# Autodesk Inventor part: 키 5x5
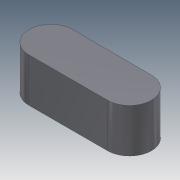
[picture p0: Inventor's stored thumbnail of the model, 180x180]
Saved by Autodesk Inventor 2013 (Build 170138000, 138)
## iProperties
Company: 한국ATC센터
Created: 2014-10
Part Number: 키 5x5
Document SubType Name: Modeling
Designer: KYOUNG IL JANG
Density: 1 g/cm^3
Mass: 0.323175 g
Surface Area: 2.9781 cm^2
Volume: 0.323175 cm^3
Material: 일반
Author: KYOUNG IL JANG
Revision Number: 1
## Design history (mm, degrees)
sketch "스케치1"
  geometry: L1 (-4.5, -2.5)-(4.5, -2.5); L2 (4.5, 2.5)-(-4.5, 2.5); A1 r 2.5 centre (4.5, 0) between (4.5, -2.5) and (4.5, 2.5); A2 r 2.5 centre (-4.5, 0) between (-4.5, 2.5) and (-4.5, -2.5); 2 further points
  constraints: 4 end point, 4 point on circle, 4 tangent, 2 centre point, 1 horizontal, 1 horizontal alignment, 1 midpoint, 1 parallel, 1 vertical alignment
  dimensions: "d0" = 5 distance between parallel lines of L1 L2; "d1" = 14 dimension on A1 A2
extrude "돌출1" new body sketch "스케치1" stored distance "d2" = 5; taper "d3" = 0 deg
node "솔리드1"
